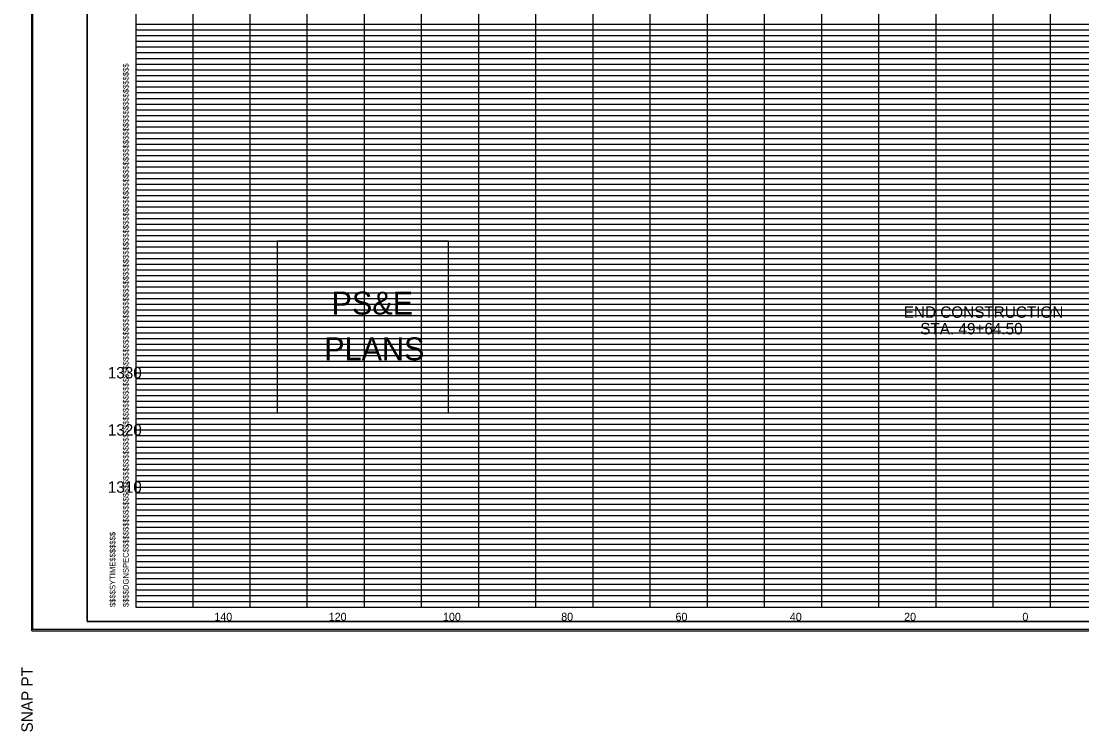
# Model space of a CAD drawing. Extents: x 980 to 1324, y 978 to 1767.
# Drawn here: x 979.9 to 1165.5, y 1518.2 to 1642.5 of the extents above; entities that cross this region are included whole.
import ezdxf

# ---------------------------------------------------------------- set-up
doc = ezdxf.new("R2010")
doc.units = 0
for name, color, linetype in [('DESIGN - SHEET - Corner Text', 7, 'Continuous'), ('DESIGN - SHEET - Light Grid', 7, 'Continuous'), ('DESIGN - SHEET - Linework', 7, 'Continuous'), ('DESIGN - SHEET - Plot Shape', 7, 'Continuous'), ('DESIGN - TYPICAL - Text', 7, 'Continuous')]:
    doc.layers.add(name, color=color, linetype=linetype)

# ---------------------------------------------------------------- blocks, each defined once
blk = doc.blocks.new('XSTSHT')
at = {"layer": 'DESIGN - SHEET - Light Grid'}
for p, q in [((0, 10.2), (8, 10.2)), ((0, 10.1), (8, 10.1)), ((8, 10.2), (16, 10.2)), ((8, 10.1), (16, 10.1)), ((16, 10.2), (24, 10.2)), ((16, 10.1), (24, 10.1)), ((0, 9.9), (8, 9.9)), ((8, 9.9), (16, 9.9)), ((16, 9.9), (24, 9.9)), ((0, 9.8), (8, 9.8)), ((0, 9.7), (8, 9.7)), ((8, 9.8), (16, 9.8)), ((8, 9.7), (16, 9.7)), ((16, 9.8), (24, 9.8)), ((16, 9.7), (24, 9.7)), ((0, 9.6), (8, 9.6)), ((0, 9.5), (8, 9.5)), ((8, 9.6), (16, 9.6)), ((8, 9.5), (16, 9.5)), ((16, 9.6), (24, 9.6)), ((16, 9.5), (24, 9.5)), ((0, 9.4), (8, 9.4)), ((0, 9.3), (8, 9.3)), ((8, 9.4), (16, 9.4)), ((8, 9.3), (16, 9.3)), ((16, 9.4), (24, 9.4)), ((16, 9.3), (24, 9.3)), ((0, 9.2), (8, 9.2)), ((0, 9.1), (8, 9.1)), ((8, 9.2), (16, 9.2)), ((8, 9.1), (16, 9.1)), ((16, 9.2), (24, 9.2)), ((16, 9.1), (24, 9.1)), ((0, 8.9), (8, 8.9)), ((0, 8.8), (8, 8.8)), ((8, 8.9), (16, 8.9)), ((8, 8.8), (16, 8.8)), ((16, 8.9), (24, 8.9)), ((16, 8.8), (24, 8.8)), ((0, 8.7), (8, 8.7)), ((0, 8.6), (8, 8.6)), ((8, 8.7), (16, 8.7)), ((8, 8.6), (16, 8.6)), ((16, 8.7), (24, 8.7)), ((16, 8.6), (24, 8.6)), ((0, 8.5), (8, 8.5)), ((0, 8.4), (8, 8.4)), ((8, 8.5), (16, 8.5)), ((8, 8.4), (16, 8.4)), ((16, 8.5), (24, 8.5)), ((16, 8.4), (24, 8.4)), ((0, 8.3), (8, 8.3)), ((0, 8.2), (8, 8.2)), ((8, 8.3), (16, 8.3)), ((8, 8.2), (16, 8.2)), ((16, 8.3), (24, 8.3)), ((16, 8.2), (24, 8.2)), ((0, 8.1), (8, 8.1)), ((8, 8.1), (16, 8.1)), ((16, 8.1), (24, 8.1)), ((0, 7.9), (8, 7.9)), ((0, 7.8), (8, 7.8)), ((8, 7.9), (16, 7.9)), ((8, 7.8), (16, 7.8)), ((16, 7.9), (24, 7.9)), ((16, 7.8), (24, 7.8)), ((0, 7.7), (8, 7.7)), ((8, 7.7), (16, 7.7)), ((16, 7.7), (24, 7.7)), ((0, 7.6), (8, 7.6)), ((0, 7.5), (8, 7.5)), ((8, 7.6), (16, 7.6)), ((8, 7.5), (16, 7.5)), ((16, 7.6), (24, 7.6)), ((16, 7.5), (24, 7.5)), ((0, 7.4), (8, 7.4)), ((0, 7.3), (8, 7.3)), ((8, 7.4), (16, 7.4)), ((8, 7.3), (16, 7.3)), ((16, 7.4), (24, 7.4)), ((16, 7.3), (24, 7.3)), ((0, 7.2), (8, 7.2)), ((0, 7.1), (8, 7.1)), ((8, 7.2), (16, 7.2)), ((8, 7.1), (16, 7.1)), ((16, 7.2), (24, 7.2)), ((16, 7.1), (24, 7.1)), ((0, 6.9), (8, 6.9)), ((8, 6.9), (16, 6.9)), ((16, 6.9), (24, 6.9)), ((0, 6.8), (8, 6.8)), ((0, 6.7), (8, 6.7)), ((8, 6.8), (16, 6.8)), ((8, 6.7), (16, 6.7)), ((16, 6.8), (24, 6.8)), ((16, 6.7), (24, 6.7)), ((0, 6.6), (8, 6.6)), ((0, 6.5), (8, 6.5)), ((8, 6.6), (16, 6.6)), ((8, 6.5), (16, 6.5)), ((16, 6.6), (24, 6.6)), ((16, 6.5), (24, 6.5)), ((0, 6.4), (8, 6.4)), ((8, 6.4), (16, 6.4)), ((16, 6.4), (24, 6.4)), ((0, 6.3), (8, 6.3)), ((0, 6.2), (8, 6.2)), ((8, 6.3), (16, 6.3)), ((8, 6.2), (16, 6.2)), ((16, 6.3), (24, 6.3)), ((16, 6.2), (24, 6.2)), ((0, 6.1), (8, 6.1)), ((8, 6.1), (16, 6.1)), ((16, 6.1), (24, 6.1)), ((0, 5.9), (8, 5.9)), ((0, 5.8), (8, 5.8)), ((8, 5.9), (16, 5.9)), ((8, 5.8), (16, 5.8)), ((16, 5.9), (24, 5.9)), ((16, 5.8), (24, 5.8)), ((0, 5.7), (8, 5.7)), ((0, 5.6), (8, 5.6)), ((8, 5.7), (16, 5.7)), ((8, 5.6), (16, 5.6)), ((16, 5.7), (24, 5.7)), ((16, 5.6), (24, 5.6)), ((0, 5.5), (8, 5.5)), ((0, 5.4), (8, 5.4)), ((8, 5.5), (16, 5.5)), ((8, 5.4), (16, 5.4)), ((16, 5.5), (24, 5.5)), ((16, 5.4), (24, 5.4)), ((0, 5.3), (8, 5.3)), ((0, 5.2), (8, 5.2)), ((8, 5.3), (16, 5.3)), ((8, 5.2), (16, 5.2)), ((16, 5.3), (24, 5.3)), ((16, 5.2), (24, 5.2)), ((0, 5.1), (8, 5.1)), ((8, 5.1), (16, 5.1)), ((16, 5.1), (24, 5.1)), ((0, 4.9), (8, 4.9)), ((8, 4.9), (16, 4.9)), ((16, 4.9), (24, 4.9)), ((0, 4.8), (8, 4.8)), ((0, 4.7), (8, 4.7)), ((8, 4.8), (16, 4.8)), ((8, 4.7), (16, 4.7)), ((16, 4.8), (24, 4.8)), ((16, 4.7), (24, 4.7)), ((0, 4.6), (8, 4.6)), ((0, 4.5), (8, 4.5)), ((8, 4.6), (16, 4.6)), ((8, 4.5), (16, 4.5)), ((16, 4.6), (24, 4.6)), ((16, 4.5), (24, 4.5)), ((0, 4.4), (8, 4.4)), ((0, 4.3), (8, 4.3)), ((8, 4.4), (16, 4.4)), ((8, 4.3), (16, 4.3)), ((16, 4.4), (24, 4.4)), ((16, 4.3), (24, 4.3)), ((0, 4.2), (8, 4.2)), ((0, 4.1), (8, 4.1)), ((8, 4.2), (16, 4.2)), ((8, 4.1), (16, 4.1)), ((16, 4.2), (24, 4.2)), ((16, 4.1), (24, 4.1)), ((0, 3.9), (8, 3.9)), ((8, 3.9), (16, 3.9)), ((16, 3.9), (24, 3.9)), ((0, 3.8), (8, 3.8)), ((8, 3.8), (16, 3.8)), ((16, 3.8), (24, 3.8)), ((0, 3.7), (8, 3.7)), ((0, 3.6), (8, 3.6)), ((8, 3.7), (16, 3.7)), ((8, 3.6), (16, 3.6)), ((16, 3.7), (24, 3.7)), ((16, 3.6), (24, 3.6)), ((0, 3.5), (8, 3.5)), ((0, 3.4), (8, 3.4)), ((8, 3.5), (16, 3.5)), ((8, 3.4), (16, 3.4)), ((16, 3.5), (24, 3.5)), ((16, 3.4), (24, 3.4)), ((0, 3.3), (8, 3.3)), ((0, 3.2), (8, 3.2)), ((8, 3.3), (16, 3.3)), ((8, 3.2), (16, 3.2)), ((16, 3.3), (24, 3.3)), ((16, 3.2), (24, 3.2)), ((0, 3.1), (8, 3.1)), ((8, 3.1), (16, 3.1)), ((16, 3.1), (24, 3.1)), ((0, 2.9), (8, 2.9)), ((0, 2.8), (8, 2.8)), ((8, 2.9), (16, 2.9)), ((8, 2.8), (16, 2.8)), ((16, 2.9), (24, 2.9)), ((16, 2.8), (24, 2.8)), ((0, 2.7), (8, 2.7)), ((0, 2.6), (8, 2.6)), ((8, 2.7), (16, 2.7)), ((8, 2.6), (16, 2.6)), ((16, 2.7), (24, 2.7)), ((16, 2.6), (24, 2.6)), ((0, 2.5), (8, 2.5)), ((8, 2.5), (16, 2.5)), ((16, 2.5), (24, 2.5)), ((0, 2.4), (8, 2.4)), ((0, 2.3), (8, 2.3)), ((8, 2.4), (16, 2.4)), ((8, 2.3), (16, 2.3)), ((16, 2.4), (24, 2.4)), ((16, 2.3), (24, 2.3)), ((0, 2.2), (8, 2.2)), ((0, 2.1), (8, 2.1)), ((8, 2.2), (16, 2.2)), ((8, 2.1), (16, 2.1)), ((16, 2.2), (24, 2.2)), ((16, 2.1), (24, 2.1)), ((0, 1.9), (8, 1.9)), ((8, 1.9), (16, 1.9)), ((16, 1.9), (24, 1.9)), ((0, 1.8), (8, 1.8)), ((0, 1.7), (8, 1.7)), ((8, 1.8), (16, 1.8)), ((8, 1.7), (16, 1.7)), ((16, 1.8), (24, 1.8)), ((16, 1.7), (24, 1.7)), ((0, 1.6), (8, 1.6)), ((0, 1.5), (8, 1.5)), ((8, 1.6), (16, 1.6)), ((8, 1.5), (16, 1.5)), ((16, 1.6), (24, 1.6)), ((16, 1.5), (24, 1.5)), ((0, 1.4), (8, 1.4)), ((0, 1.3), (8, 1.3)), ((8, 1.4), (16, 1.4)), ((8, 1.3), (16, 1.3)), ((16, 1.4), (24, 1.4)), ((16, 1.3), (24, 1.3)), ((0, 1.2), (8, 1.2)), ((8, 1.2), (16, 1.2)), ((16, 1.2), (24, 1.2)), ((0, 1.1), (8, 1.1)), ((8, 1.1), (16, 1.1)), ((16, 1.1), (24, 1.1)), ((0, 0.9), (8, 0.9)), ((0, 0.8), (8, 0.8)), ((8, 0.9), (16, 0.9)), ((8, 0.8), (16, 0.8)), ((16, 0.9), (24, 0.9)), ((16, 0.8), (24, 0.8)), ((0, 0.7), (8, 0.7)), ((0, 0.6), (8, 0.6)), ((8, 0.7), (16, 0.7)), ((8, 0.6), (16, 0.6)), ((16, 0.7), (24, 0.7)), ((16, 0.6), (24, 0.6)), ((0, 0.5), (8, 0.5)), ((0, 0.4), (8, 0.4)), ((8, 0.5), (16, 0.5)), ((8, 0.4), (16, 0.4)), ((16, 0.5), (24, 0.5)), ((16, 0.4), (24, 0.4)), ((0, 0.3), (8, 0.3)), ((0, 0.2), (8, 0.2)), ((8, 0.3), (16, 0.3)), ((8, 0.2), (16, 0.2)), ((16, 0.3), (24, 0.3)), ((16, 0.2), (24, 0.2)), ((0, 0.1), (8, 0.1)), ((8, 0.1), (16, 0.1)), ((16, 0.1), (24, 0.1))]:
    blk.add_line(p, q, dxfattribs=at)
at = {"layer": 'DESIGN - SHEET - Linework'}
for p, q in [((-1.823, -0.414), (-1.823, 21.414)), ((1, 0), (1, 21)), ((2, 0), (2, 21)), ((3, 0), (3, 21)), ((4, 0), (4, 21)), ((5, 0), (5, 21)), ((6, 0), (6, 21)), ((7, 0), (7, 21)), ((8, 0), (8, 21)), ((9, 0), (9, 21)), ((10, 0), (10, 21)), ((11, 0), (11, 21)), ((12, 0), (12, 21)), ((13, 0), (13, 21)), ((14, 0), (14, 21)), ((15, 0), (15, 21)), ((16, 0), (16, 21)), ((0, 10), (32, 10)), ((0, 9), (32, 9)), ((0, 8), (32, 8)), ((0, 7), (32, 7)), ((0, 6), (32, 6)), ((0, 5), (32, 5)), ((0, 4), (32, 4)), ((0, 3), (32, 3)), ((0, 2), (32, 2)), ((0, 1), (32, 1)), ((-1.823, -0.414), (32.217, -0.414))]:
    blk.add_line(p, q, dxfattribs=at)
blk.add_lwpolyline([(0, 21), (0, 0), (32, 0), (32, 21), (0, 21)], dxfattribs=at)
at = {"layer": 'DESIGN - SHEET - Plot Shape'}
for points in [[(-1.803, 21.394), (32.197, 21.394), (32.197, -0.394), (-1.803, -0.394)], [(-0.85, 21), (32, 21), (32, -0.25), (-0.85, -0.25)]]:
    blk.add_lwpolyline(points, close=True, dxfattribs=at)
at = {"layer": 'DESIGN - SHEET - Corner Text'}
for s, height, p in [('$$$$DGNSPEC$$$$$$$$$$$$$$$$$$$$$$$$$$$$$$$$$$$$$$$$$$$$$$$$$$$$$$$$$$$$$$$$$$$$$$$$$$$$$$$$$$$$$$$$$$$$$$$$$$$$$$$$$$$$$$$$$$$', 0.100002, (-0.126, 0)), ('$$$$SYTIME$$$$$$$', 0.1, (-0.358, 0)), ('SNAP PT  ', 0.2, (-1.803, -2.194))]:
    blk.add_text(s, height=height, rotation=90, dxfattribs=at).set_placement(p)

msp = doc.modelspace()

# ---------------------------------------------------------------- linework, layer by layer
at = {"layer": 'DESIGN - SHEET - Corner Text'}
msp.add_lwpolyline([(1024.71, 1604), (1024.71, 1574), (1054.71, 1574), (1054.71, 1604)], close=True, dxfattribs=at)
at = {"layer": 'DESIGN - SHEET - Plot Shape'}
msp.add_lwpolyline([(991.5, 1537.5), (1320, 1537.5), (1320, 1750), (991.5, 1750)], close=True, dxfattribs=at)

# ---------------------------------------------------------------- block references
at = {"layer": 'DESIGN - SHEET - Plot Shape', "xscale": 10, "yscale": 10}
msp.add_blockref('XSTSHT', (1000, 1540), dxfattribs=at)

# ---------------------------------------------------------------- texts
at = {"layer": 'DESIGN - SHEET - Corner Text'}
for s, p in [('PS&E', (1034.23, 1591.18)), ('PLANS', (1032.95, 1583.18))]:
    msp.add_text(s, height=4, dxfattribs=at).set_placement(p)
at = {"layer": 'DESIGN - TYPICAL - Text'}
for s, height, p in [('END CONSTRUCTION', 2, (1134.35, 1590.61)), ('STA. 49+64.50', 2, (1137.24, 1587.71)), ('     1330     ', 2, (991.37, 1580)), ('     1320     ', 2, (991.37, 1570)), ('     1310     ', 2, (991.37, 1560)), ('     140     ', 1.4, (1011.14, 1537.6)), ('     120     ', 1.4, (1031.14, 1537.6)), ('     100     ', 1.4, (1051.14, 1537.6)), ('     80     ', 1.4, (1071.82, 1537.6)), ('     60     ', 1.4, (1091.82, 1537.6)), ('     40     ', 1.4, (1111.82, 1537.6)), ('     20     ', 1.4, (1131.82, 1537.6)), ('     0     ', 1.4, (1152.51, 1537.6)), ('     0     ', 1.4, (1152.51, 1537.6))]:
    msp.add_text(s, height=height, dxfattribs=at).set_placement(p)

doc.saveas('drawing.dxf')
